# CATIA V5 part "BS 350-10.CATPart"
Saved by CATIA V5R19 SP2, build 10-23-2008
Part number: BS 300-10
Bounding box of the stored display mesh (mm): x -15.868 to 15.868, y -15.868 to 15.868, z 0 to 50
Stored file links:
  C:\Users\Bora\Desktop\3D Katı model\BS serisi\BS 300\BS 300-10.CATPart
  C:\Program Files\Dassault Systemes\B19\intel_a\reffiles\standard\MetricThickPitch.txt
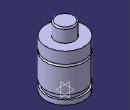
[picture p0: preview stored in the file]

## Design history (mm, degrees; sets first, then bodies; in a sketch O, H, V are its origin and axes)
Body1 (main body)
  Sketch1 on yz-plane, origin (0, 0, 0), H (0, 1, 0), V (0, 0, 1)
    point P1 (8, 49)
    point P3 (8, 49)
    point P5 (16, 29.5)
    point P6 (16, 27.5)
    point P9 (16, 29.5)
    point P14 (16, 27.5)
    line L1 (8, 49) -> (8, 39)
    arc A1 centre (7, 49) radius 1 from (8, 49) to (7, 50) ccw
    arc A2 centre (16, 28.5) radius 1 from (16, 29.5) to (16, 27.5) ccw
    line L2 (16, 0) -> (16, 4)
    line L3 (16, 29.5) -> (16, 39)
    line L4 (14.5, 7.5) -> (14.5, 4)
    line L5 (16, 7.5) -> (16, 27.5)
    line L6 (7, 50) -> (0, 50)
    point P15 (0, 50)
    line L7 (8, 39) -> (16, 39)
    line L8 (0, 0) -> (16, 0)
    line L9 (14.5, 4) -> (16, 4)
    line L10 (14.5, 7.5) -> (16, 7.5)
    tangency: L6 A1
    coincidence: P15 V, P1 P3, P5 P9, P6 P14
    horizontal: L7 H, L8 H, L9 H, L10 H
  Shaft1: profile Sketch1, axis Sketch1.V, angle 360
  Sketch2 on face of Shaft1 from Sketch1.L8, origin (0, 0, 0), H (1, 0, 0), V (0, -1, 0)
    point P1 (0, 0)
  Hole1: placed by Sketch2, at (0, 0, 0) direction (0, 0, 1), diameter 6.647, depth 4, threaded "M8", thread diameter 8, thread depth 4, pitch 1.25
